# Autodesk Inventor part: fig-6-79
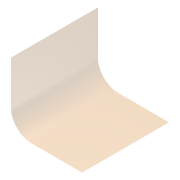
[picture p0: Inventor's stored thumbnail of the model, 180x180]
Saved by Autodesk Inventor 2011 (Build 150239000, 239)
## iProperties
Shininess: 64.0
Length Units: 11269
Angle Units: 11279
Time Units: 11290
Mass Units: 11283
Length Display Precision: 3
Angle Display Precision: 2
Compacted: True
Part Number: fig-6-79
Document SubType Name: Modeling
Created: 2003-10
Designer: Owner
Manufacturer: Standard
Standards Organization: Custom
Density: 1 g/cm^3
Density: 0.0
Volumn: 0.0
Area: 0.0
PropertySet Name: Model Information
Control State: 0
Master: False
Checked Out: False
Author: Owner
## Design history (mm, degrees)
node "Sketch1"
sketch "Sketch2"
  geometry: L1 (22.777, 31.862)-(22.777, 0.2); L2 (7.777, -14.8)-(-29.161, -14.8); A1 r 15 centre (7.777, 0.2) between (7.777, -14.8) and (22.777, 0.2)
  constraints: 4 end point, 2 point on circle, 2 tangent, 1 centre point, 1 perpendicular, 1 vertical
  dimensions: "d23" = 15 radius of A1
extrude_surface "ExtrusionSrf1" sketch "Sketch2" dims "d24" = 63.5, "d25" = 0
body "Srf1"
